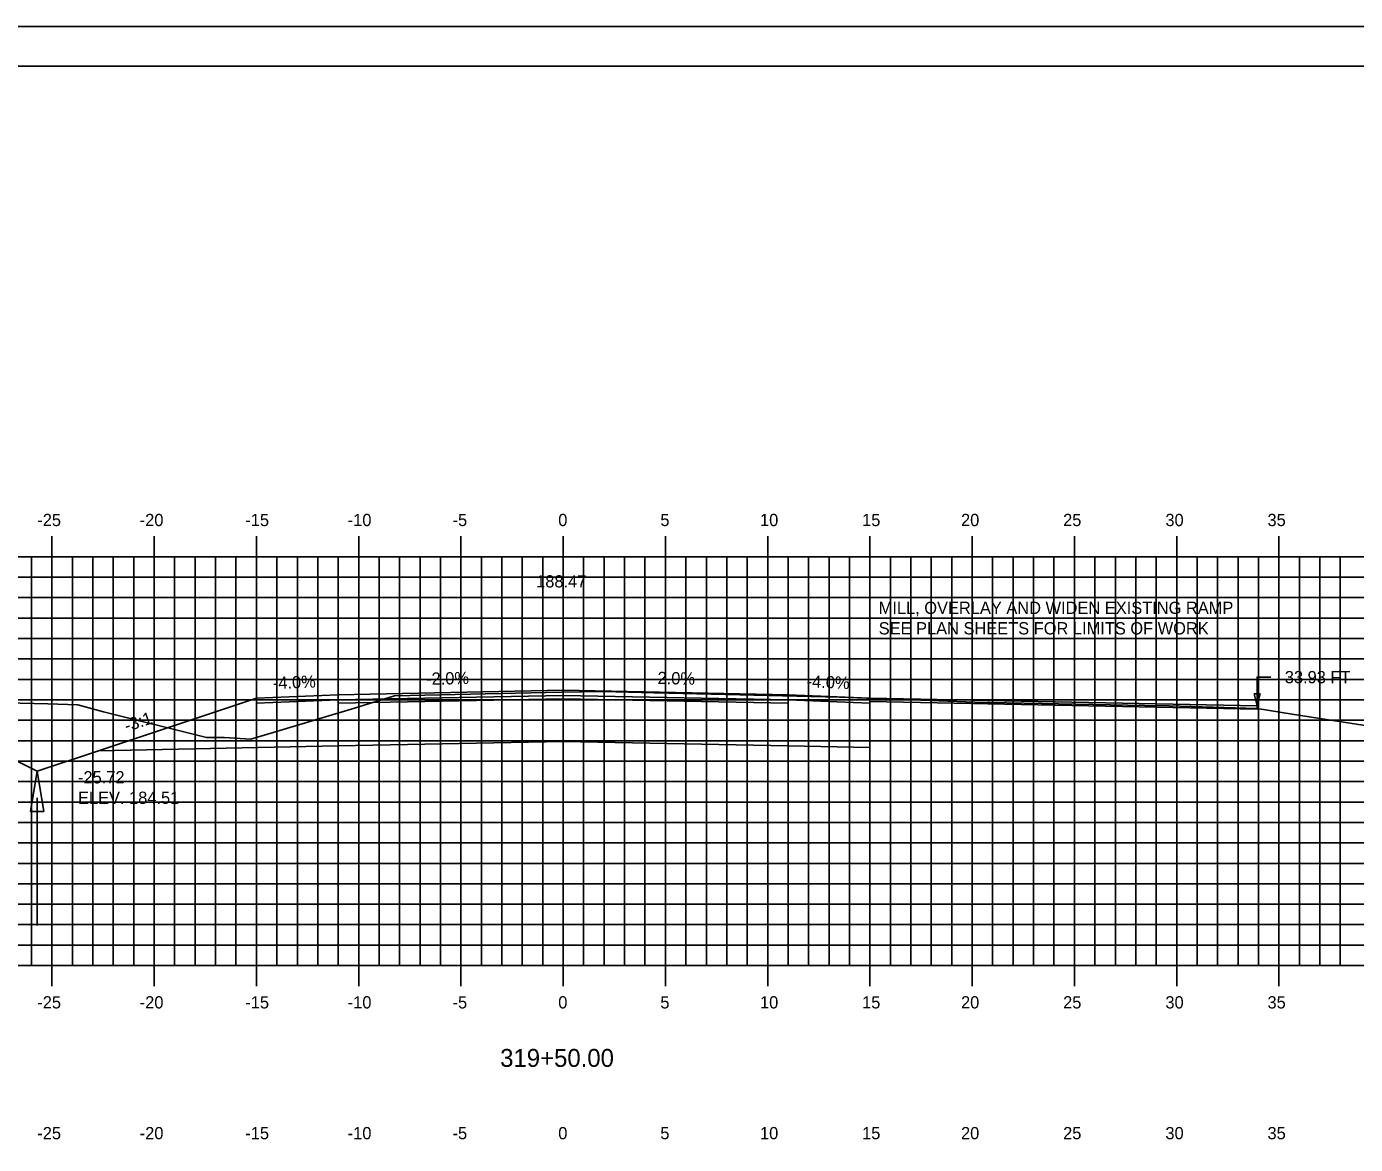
# Model space of a CAD drawing. Extents: x 1139428 to 1139598, y 608981 to 609091.
# Drawn here: x 1139485.2 to 1139550.2, y 609036.6 to 609091.3 of the extents above; entities that cross this region are included whole.
import ezdxf

# ---------------------------------------------------------------- set-up
doc = ezdxf.new("R2010")
doc.units = 0
for name, color, linetype in [('ANNOTATION', 7, 'Continuous'), ('BORDER', 7, 'Continuous'), ('D_Drainage_Ditch_Line', 7, 'Continuous'), ('D_Roadway_Centerline', 7, 'Continuous'), ('D_Roadway_Centerline_Text', 7, 'Continuous'), ('D_Roadway_Edge_Shoulder', 7, 'Continuous'), ('D_Roadway_Edge_TW', 7, 'Continuous'), ('D_Roadway_Pavement', 7, 'Continuous'), ('D_Roadway_SlopeLines', 7, 'Continuous'), ('D_Roadway_SubGrade', 7, 'Continuous'), ('D_Text_Standard', 7, 'Continuous'), ('H_V ANNOTATION', 7, 'Continuous'), ('MAJOR', 7, 'Continuous'), ('MINOR', 7, 'Continuous'), ('PLOT BOUNDARY', 7, 'Continuous'), ('S_Roadway_Centerline', 7, 'Continuous')]:
    doc.layers.add(name, color=color, linetype=linetype)

msp = doc.modelspace()

# ---------------------------------------------------------------- linework, layer by layer
msp.add_lwpolyline([(1139476.282, 609058.385), (1139477.532, 609058.28), (1139478.782, 609058.027), (1139480.032, 609057.625), (1139481.282, 609057.074), (1139485.737, 609054.846), (1139488.737, 609055.846), (1139496.461, 609058.421), (1139496.462, 609058.421), (1139500.462, 609058.581), (1139511.462, 609058.801), (1139522.462, 609058.581), (1139526.462, 609058.421)])
at = {"layer": 'BORDER'}
msp.add_lwpolyline([(1139436.462, 608984.335), (1139596.462, 608984.335), (1139596.462, 609089.335), (1139436.462, 609089.335)], close=True, dxfattribs=at)
at = {"layer": 'D_Drainage_Ditch_Line'}
msp.add_line((1139485.737, 609053.534), (1139485.737, 609047.291), dxfattribs=at)
msp.add_lwpolyline([(1139486.065, 609052.878), (1139485.409, 609052.878), (1139485.737, 609054.846)], close=True, dxfattribs=at)
at = {"layer": 'D_Roadway_Edge_Shoulder'}
for points in [[(1139500.462, 609058.581), (1139496.462, 609058.421), (1139496.462, 609058.171), (1139500.462, 609058.331)], [(1139522.462, 609058.581), (1139526.462, 609058.421), (1139526.462, 609058.171), (1139522.462, 609058.331)]]:
    msp.add_lwpolyline(points, close=True, dxfattribs=at)
for points in [[(1139545.393, 609057.918), (1139545.393, 609058.043), (1139526.462, 609058.421)], [(1139526.462, 609058.421), (1139526.462, 609058.254), (1139545.39, 609057.877), (1139545.393, 609058.043)]]:
    msp.add_lwpolyline(points, dxfattribs=at)
at = {"layer": 'D_Roadway_Edge_TW'}
msp.add_lwpolyline([(1139500.462, 609058.331), (1139500.462, 609058.581), (1139511.462, 609058.801), (1139522.462, 609058.581), (1139522.462, 609058.331), (1139511.462, 609058.551)], close=True, dxfattribs=at)
at = {"layer": 'D_Roadway_Pavement'}
msp.add_lwpolyline([(1139500.462, 609058.164), (1139500.462, 609058.331), (1139511.462, 609058.551), (1139522.462, 609058.331), (1139522.462, 609058.164), (1139511.462, 609058.384)], close=True, dxfattribs=at)
at = {"layer": 'D_Roadway_SlopeLines'}
for points in [[(1139485.737, 609054.846), (1139481.282, 609057.074), (1139480.032, 609057.625), (1139478.782, 609058.027), (1139477.532, 609058.28), (1139476.282, 609058.385)], [(1139488.737, 609055.846), (1139485.737, 609054.846)]]:
    msp.add_lwpolyline(points, dxfattribs=at)
at = {"layer": 'D_Roadway_SubGrade'}
for points in [[(1139500.462, 609058.164), (1139500.462, 609058.331), (1139496.462, 609058.171), (1139496.462, 609058.421), (1139496.461, 609058.421), (1139488.737, 609055.846), (1139500.462, 609056.081)], [(1139500.462, 609056.081), (1139500.462, 609058.164), (1139511.462, 609058.384), (1139522.462, 609058.164), (1139522.462, 609056.081), (1139511.462, 609056.301)], [(1139526.462, 609057.421), (1139526.462, 609058.421), (1139526.462, 609058.421), (1139526.462, 609058.171), (1139522.462, 609058.331), (1139522.462, 609058.164), (1139522.462, 609056.081), (1139526.462, 609056.001)]]:
    msp.add_lwpolyline(points, close=True, dxfattribs=at)
at = {"layer": 'D_Text_Standard'}
msp.add_lwpolyline([(1139545.393, 609058.043), (1139545.389, 609059.445), (1139546.069, 609059.445)], dxfattribs=at)
msp.add_lwpolyline([(1139545.393, 609058.043), (1139545.246, 609058.625), (1139545.537, 609058.626)], close=True, dxfattribs=at)
at = {"layer": 'MAJOR'}
for p, q in [((1139486.462, 609066.337), (1139486.462, 609065.335)), ((1139491.462, 609066.337), (1139491.462, 609065.335)), ((1139496.462, 609066.337), (1139496.462, 609065.335)), ((1139501.462, 609066.337), (1139501.462, 609065.335)), ((1139506.462, 609066.337), (1139506.462, 609065.335)), ((1139511.462, 609066.337), (1139511.462, 609065.335)), ((1139516.462, 609066.337), (1139516.462, 609065.335)), ((1139521.462, 609066.337), (1139521.462, 609065.335)), ((1139526.462, 609066.337), (1139526.462, 609065.335)), ((1139531.462, 609066.337), (1139531.462, 609065.335)), ((1139536.462, 609066.337), (1139536.462, 609065.335)), ((1139541.462, 609066.337), (1139541.462, 609065.335)), ((1139546.462, 609066.337), (1139546.462, 609065.335)), ((1139441.462, 609065.335), (1139581.462, 609065.335)), ((1139441.462, 609065.335), (1139581.462, 609065.335)), ((1139486.462, 609045.335), (1139486.462, 609065.335)), ((1139491.462, 609045.335), (1139491.462, 609065.335)), ((1139496.462, 609045.335), (1139496.462, 609065.335)), ((1139501.462, 609045.335), (1139501.462, 609065.335)), ((1139506.462, 609045.335), (1139506.462, 609065.335)), ((1139511.462, 609045.335), (1139511.462, 609065.335)), ((1139516.462, 609045.335), (1139516.462, 609065.335)), ((1139521.462, 609045.335), (1139521.462, 609065.335)), ((1139526.462, 609045.335), (1139526.462, 609065.335)), ((1139531.462, 609045.335), (1139531.462, 609065.335)), ((1139536.462, 609045.335), (1139536.462, 609065.335)), ((1139541.462, 609045.335), (1139541.462, 609065.335)), ((1139546.462, 609045.335), (1139546.462, 609065.335)), ((1139441.462, 609060.335), (1139581.462, 609060.335)), ((1139441.462, 609055.335), (1139581.462, 609055.335)), ((1139441.462, 609050.335), (1139581.462, 609050.335)), ((1139441.462, 609045.335), (1139581.462, 609045.335)), ((1139441.462, 609045.335), (1139581.462, 609045.335)), ((1139486.462, 609044.333), (1139486.462, 609045.335)), ((1139491.462, 609044.333), (1139491.462, 609045.335)), ((1139496.462, 609044.333), (1139496.462, 609045.335)), ((1139501.462, 609044.333), (1139501.462, 609045.335)), ((1139506.462, 609044.333), (1139506.462, 609045.335)), ((1139511.462, 609044.333), (1139511.462, 609045.335)), ((1139516.462, 609044.333), (1139516.462, 609045.335)), ((1139521.462, 609044.333), (1139521.462, 609045.335)), ((1139526.462, 609044.333), (1139526.462, 609045.335)), ((1139531.462, 609044.333), (1139531.462, 609045.335)), ((1139536.462, 609044.333), (1139536.462, 609045.335)), ((1139541.462, 609044.333), (1139541.462, 609045.335)), ((1139546.462, 609044.333), (1139546.462, 609045.335))]:
    msp.add_line(p, q, dxfattribs=at)
at = {"layer": 'MINOR'}
for p, q in [((1139485.462, 609045.335), (1139485.462, 609065.335)), ((1139487.462, 609045.335), (1139487.462, 609065.335)), ((1139488.462, 609045.335), (1139488.462, 609065.335)), ((1139489.462, 609045.335), (1139489.462, 609065.335)), ((1139490.462, 609045.335), (1139490.462, 609065.335)), ((1139492.462, 609045.335), (1139492.462, 609065.335)), ((1139493.462, 609045.335), (1139493.462, 609065.335)), ((1139494.462, 609045.335), (1139494.462, 609065.335)), ((1139495.462, 609045.335), (1139495.462, 609065.335)), ((1139497.462, 609045.335), (1139497.462, 609065.335)), ((1139498.462, 609045.335), (1139498.462, 609065.335)), ((1139499.462, 609045.335), (1139499.462, 609065.335)), ((1139500.462, 609045.335), (1139500.462, 609065.335)), ((1139502.462, 609045.335), (1139502.462, 609065.335)), ((1139503.462, 609045.335), (1139503.462, 609065.335)), ((1139504.462, 609045.335), (1139504.462, 609065.335)), ((1139505.462, 609045.335), (1139505.462, 609065.335)), ((1139507.462, 609045.335), (1139507.462, 609065.335)), ((1139508.462, 609045.335), (1139508.462, 609065.335)), ((1139509.462, 609045.335), (1139509.462, 609065.335)), ((1139510.462, 609045.335), (1139510.462, 609065.335)), ((1139512.462, 609045.335), (1139512.462, 609065.335)), ((1139513.462, 609045.335), (1139513.462, 609065.335)), ((1139514.462, 609045.335), (1139514.462, 609065.335)), ((1139515.462, 609045.335), (1139515.462, 609065.335)), ((1139517.462, 609045.335), (1139517.462, 609065.335)), ((1139518.462, 609045.335), (1139518.462, 609065.335)), ((1139519.462, 609045.335), (1139519.462, 609065.335)), ((1139520.462, 609045.335), (1139520.462, 609065.335)), ((1139522.462, 609045.335), (1139522.462, 609065.335)), ((1139523.462, 609045.335), (1139523.462, 609065.335)), ((1139524.462, 609045.335), (1139524.462, 609065.335)), ((1139525.462, 609045.335), (1139525.462, 609065.335)), ((1139527.462, 609045.335), (1139527.462, 609065.335)), ((1139528.462, 609045.335), (1139528.462, 609065.335)), ((1139529.462, 609045.335), (1139529.462, 609065.335)), ((1139530.462, 609045.335), (1139530.462, 609065.335)), ((1139532.462, 609045.335), (1139532.462, 609065.335)), ((1139533.462, 609045.335), (1139533.462, 609065.335)), ((1139534.462, 609045.335), (1139534.462, 609065.335)), ((1139535.462, 609045.335), (1139535.462, 609065.335)), ((1139537.462, 609045.335), (1139537.462, 609065.335)), ((1139538.462, 609045.335), (1139538.462, 609065.335)), ((1139539.462, 609045.335), (1139539.462, 609065.335)), ((1139540.462, 609045.335), (1139540.462, 609065.335)), ((1139542.462, 609045.335), (1139542.462, 609065.335)), ((1139543.462, 609045.335), (1139543.462, 609065.335)), ((1139544.462, 609045.335), (1139544.462, 609065.335)), ((1139545.462, 609045.335), (1139545.462, 609065.335)), ((1139547.462, 609045.335), (1139547.462, 609065.335)), ((1139548.462, 609045.335), (1139548.462, 609065.335)), ((1139549.462, 609045.335), (1139549.462, 609065.335)), ((1139441.462, 609064.335), (1139581.462, 609064.335)), ((1139441.462, 609063.335), (1139581.462, 609063.335)), ((1139441.462, 609062.335), (1139581.462, 609062.335)), ((1139441.462, 609061.335), (1139581.462, 609061.335)), ((1139441.462, 609059.335), (1139581.462, 609059.335)), ((1139441.462, 609058.335), (1139581.462, 609058.335)), ((1139441.462, 609057.335), (1139581.462, 609057.335)), ((1139441.462, 609056.335), (1139581.462, 609056.335)), ((1139441.462, 609054.335), (1139581.462, 609054.335)), ((1139441.462, 609053.335), (1139581.462, 609053.335)), ((1139441.462, 609052.335), (1139581.462, 609052.335)), ((1139441.462, 609051.335), (1139581.462, 609051.335)), ((1139441.462, 609049.335), (1139581.462, 609049.335)), ((1139441.462, 609048.335), (1139581.462, 609048.335)), ((1139441.462, 609047.335), (1139581.462, 609047.335)), ((1139441.462, 609046.335), (1139581.462, 609046.335))]:
    msp.add_line(p, q, dxfattribs=at)
at = {"layer": 'PLOT BOUNDARY'}
msp.add_lwpolyline([(1139428.369, 608981.276), (1139598.369, 608981.276), (1139598.369, 609091.276), (1139428.369, 609091.276)], close=True, dxfattribs=at)
at = {"layer": 'S_Roadway_Centerline'}
msp.add_lwpolyline([(1139468.652, 609058.571), (1139486.265, 609058.142), (1139487.722, 609058.092), (1139488.987, 609057.755), (1139494.018, 609056.497), (1139494.879, 609056.489), (1139496.181, 609056.41), (1139501.09, 609057.876), (1139503.214, 609058.528), (1139511.386, 609058.702), (1139513.391, 609058.742), (1139513.398, 609058.736), (1139515.904, 609058.684), (1139524.966, 609058.472), (1139532.027, 609058.207), (1139532.052, 609058.206), (1139532.302, 609058.202), (1139538.233, 609058.097), (1139539.889, 609058.057), (1139541.088, 609058.035), (1139545.393, 609057.918), (1139547.101, 609057.635), (1139552.673, 609056.771)], dxfattribs=at)

# ---------------------------------------------------------------- texts
at = {"layer": 'ANNOTATION'}
for s, p in [('MILL, OVERLAY AND WIDEN EXISTING RAMP', (1139526.89, 609062.537)), ('SEE PLAN SHEETS FOR LIMITS OF WORK', (1139526.89, 609061.535))]:
    msp.add_text(s, height=0.6, dxfattribs=at).set_placement(p)
for s, rotation, p in [('-2.0%', 1.14576, (1139504.765, 609059.067)), ('-2.0%', 358.85424, (1139515.805, 609059.114)), ('-4.0%', 2.29061, (1139497.278, 609058.854)), ('-4.0%', 357.70939, (1139523.358, 609058.946)), ('-3:1', 18.43482, (1139490.116, 609056.76))]:
    msp.add_text(s, height=0.6, rotation=rotation, dxfattribs=at).set_placement(p)
at = {"layer": 'D_Roadway_Centerline'}
for s, p in [('C', (1139511.457, 609058.801)), ('L', (1139511.462, 609058.794))]:
    msp.add_text(s, height=0.0146, dxfattribs=at).set_placement(p)
at = {"layer": 'D_Roadway_Centerline_Text'}
msp.add_text('188.47', height=0.6, dxfattribs=at).set_placement((1139510.14, 609063.833))
at = {"layer": 'D_Text_Standard'}
for s, p in [('33.93 FT', (1139546.749, 609059.145)), ('-25.72', (1139487.737, 609054.246)), ('ELEV. 184.51', (1139487.737, 609053.244))]:
    msp.add_text(s, height=0.6, dxfattribs=at).set_placement(p)
at = {"layer": 'H_V ANNOTATION'}
for s, height, p in [('-25', 0.6, (1139485.747, 609066.835)), ('-20', 0.6, (1139490.755, 609066.835)), ('-15', 0.6, (1139495.919, 609066.835)), ('-10', 0.6, (1139500.927, 609066.835)), ('-5', 0.6, (1139506.052, 609066.835)), ('0', 0.6, (1139511.221, 609066.835)), ('5', 0.6, (1139516.213, 609066.835)), ('10', 0.6, (1139521.087, 609066.835)), ('15', 0.6, (1139526.079, 609066.835)), ('20', 0.6, (1139530.916, 609066.835)), ('25', 0.6, (1139535.908, 609066.835)), ('30', 0.6, (1139540.91, 609066.835)), ('35', 0.6, (1139545.902, 609066.835)), ('-25', 0.6, (1139485.747, 609043.235)), ('-20', 0.6, (1139490.755, 609043.235)), ('-15', 0.6, (1139495.919, 609043.235)), ('-10', 0.6, (1139500.927, 609043.235)), ('-5', 0.6, (1139506.052, 609043.235)), ('0', 0.6, (1139511.221, 609043.235)), ('5', 0.6, (1139516.213, 609043.235)), ('10', 0.6, (1139521.087, 609043.235)), ('15', 0.6, (1139526.079, 609043.235)), ('20', 0.6, (1139530.916, 609043.235)), ('25', 0.6, (1139535.908, 609043.235)), ('30', 0.6, (1139540.91, 609043.235)), ('35', 0.6, (1139545.902, 609043.235)), ('319+50.00', 0.875, (1139508.38, 609040.378)), ('-25', 0.6, (1139485.747, 609036.835)), ('-20', 0.6, (1139490.755, 609036.835)), ('-15', 0.6, (1139495.919, 609036.835)), ('-10', 0.6, (1139500.927, 609036.835)), ('-5', 0.6, (1139506.052, 609036.835)), ('0', 0.6, (1139511.221, 609036.835)), ('5', 0.6, (1139516.213, 609036.835)), ('10', 0.6, (1139521.087, 609036.835)), ('15', 0.6, (1139526.079, 609036.835)), ('20', 0.6, (1139530.916, 609036.835)), ('25', 0.6, (1139535.908, 609036.835)), ('30', 0.6, (1139540.91, 609036.835)), ('35', 0.6, (1139545.902, 609036.835))]:
    msp.add_text(s, height=height, dxfattribs=at).set_placement(p)
at = {"layer": 'S_Roadway_Centerline'}
for s, p in [('C', (1139513.386, 609058.69)), ('L', (1139513.391, 609058.683)), ('C', (1139513.392, 609058.736)), ('L', (1139513.398, 609058.729))]:
    msp.add_text(s, height=0.0146, dxfattribs=at).set_placement(p)

doc.saveas('drawing.dxf')
